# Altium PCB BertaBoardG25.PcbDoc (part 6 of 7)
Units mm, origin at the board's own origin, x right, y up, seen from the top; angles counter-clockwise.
Board outline 160 x 160 mm, 4 copper layers (Top, GND Plane, Power Plane, Bottom), stack 1.344 mm thick; 17 components, 112 nets, 2311 pads, 138 vias.
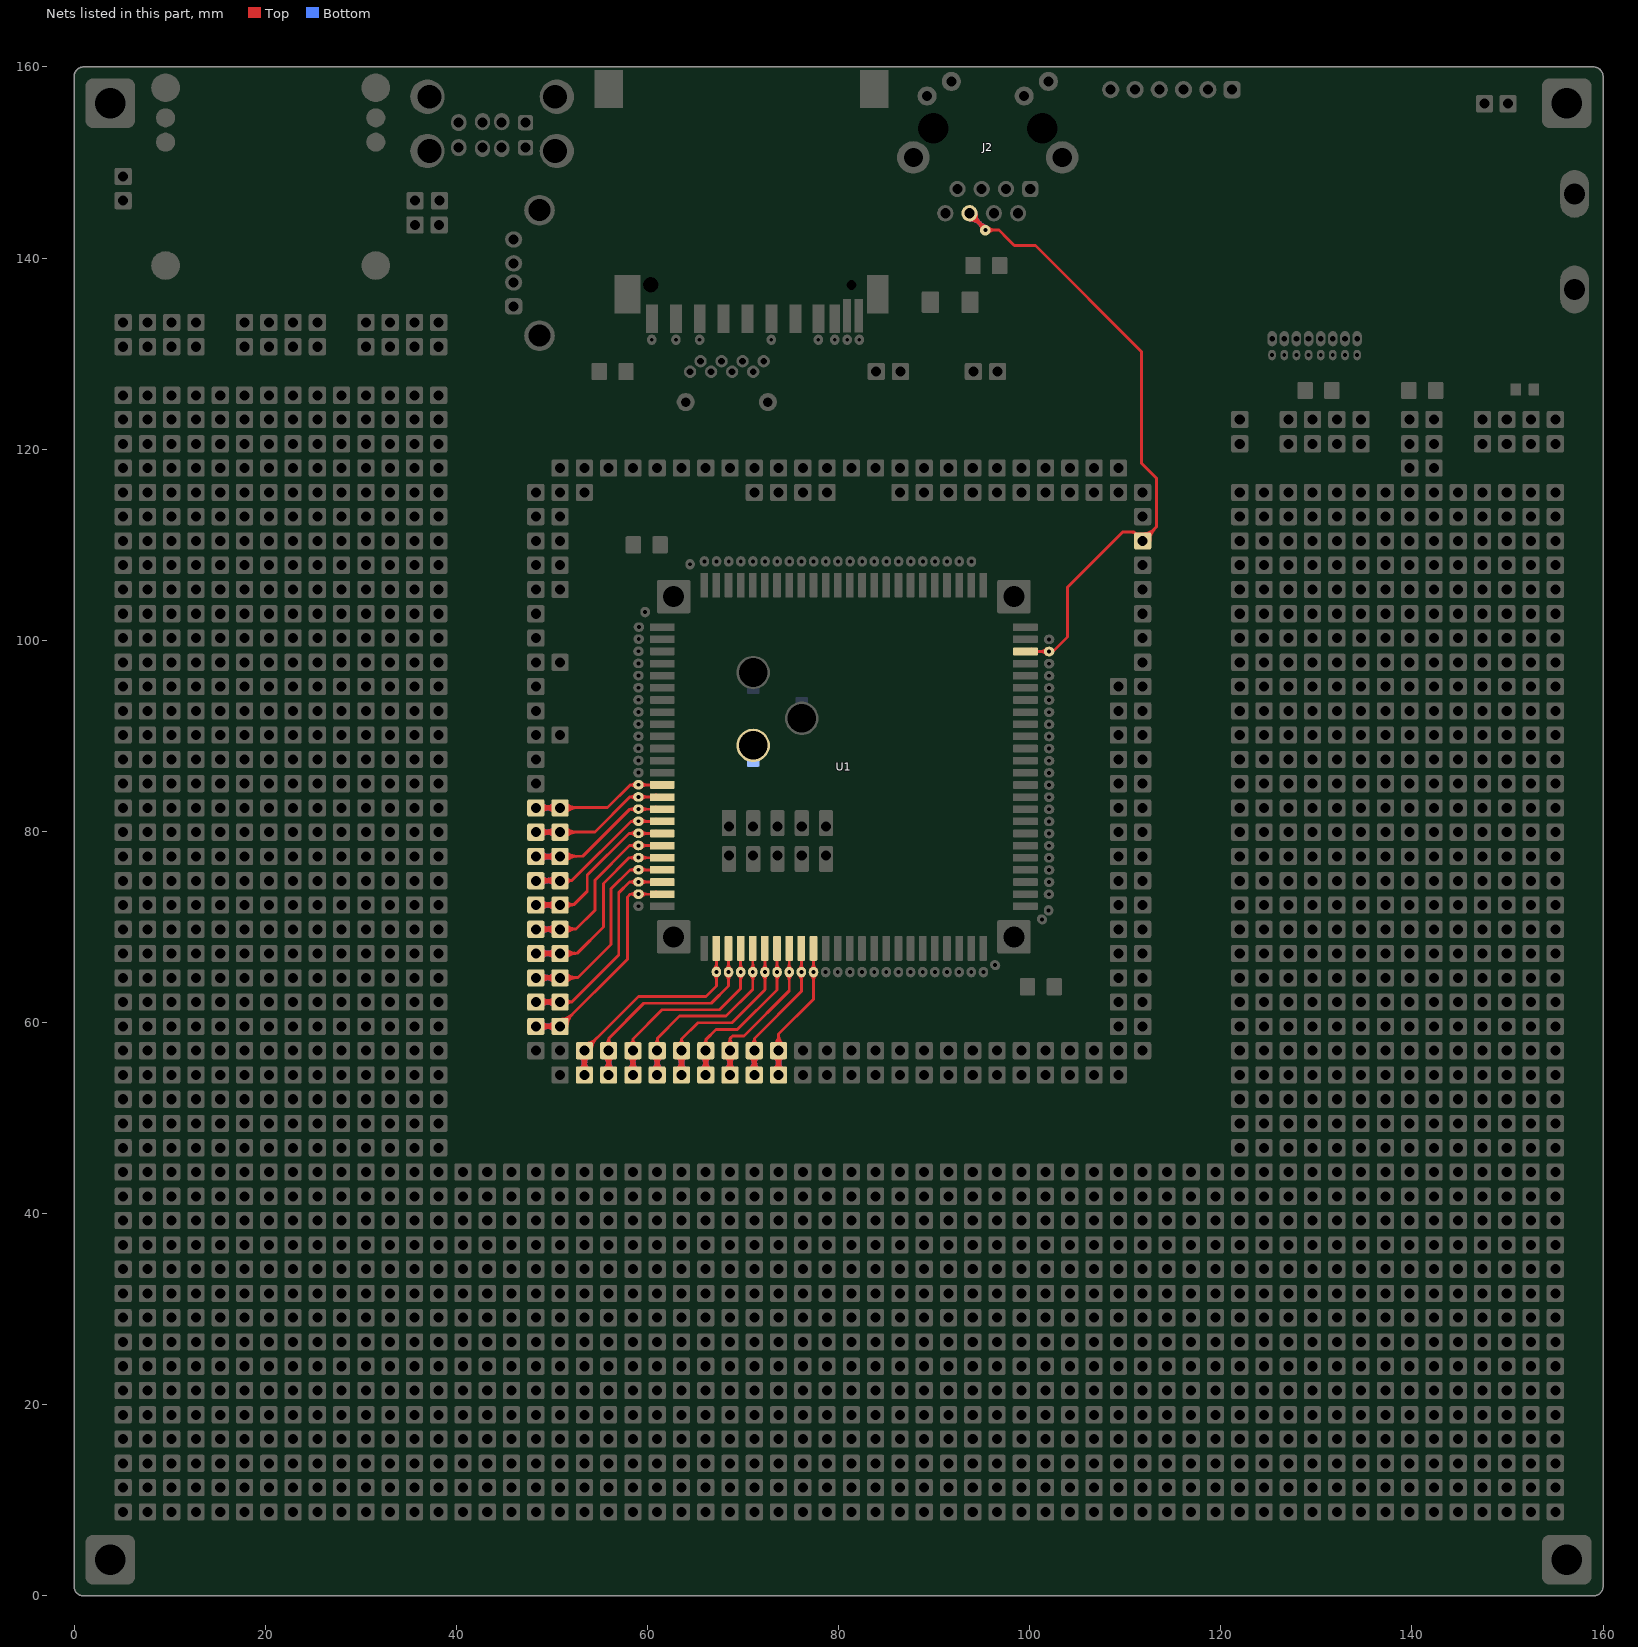
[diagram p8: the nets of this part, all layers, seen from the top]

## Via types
v1: diameter 1.5, hole 0.7, Top to Bottom, tented both sides, 54 vias
v2: diameter 1.1, hole 0.4, Top to Bottom, tented both sides, 49 vias
v3: diameter 1.9, hole 1.05, Top to Bottom, tented both sides, 17 vias
v4: diameter 1.9, hole 1.05, Top to Bottom, 16 vias
v5: diameter 0.9, hole 0.4, Top to Bottom, tented both sides, 2 vias

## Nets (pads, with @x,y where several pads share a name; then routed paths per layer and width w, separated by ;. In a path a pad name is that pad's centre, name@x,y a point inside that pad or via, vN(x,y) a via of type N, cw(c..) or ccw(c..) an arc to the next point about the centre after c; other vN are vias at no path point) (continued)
PC13: pad.0@73.722,54.52 pad.0@73.722,57.06 pad.0@77.379,65.279 U1.N15 | length 52.4
  Top w0.3: pad.0@73.191,55.05 ccw(c71.888,56.353) pad.0@73.731,56.353 ; pad.0@73.191,56.529 cw(c71.888,55.226) pad.0@73.731,55.226 ; pad.0@73.212,57.609 ccw(c72.108,58.8) 73.731,58.8 ; pad.0@73.311,56.432 cw(c72.971,55.913) 73.57,55.753 cw(c74.581,55.482) pad.0@74.081,56.401 ; pad.0@73.359,56.403 cw(c72.829,55.445) 73.886,55.729 cw(c74.524,55.9) pad.0@74.148,56.443 ; pad.0@73.404,54.838 ccw(c72.613,55.629) 73.731,55.629 ; pad.0@73.404,56.741 cw(c72.613,55.95) 73.731,55.95 ; pad.0@73.416,57.39 ccw(c72.745,58.112) 73.731,58.112 ; pad.0@73.475,56.683 cw(c73.21,56.278) 73.678,56.153 ; pad.0@73.731,54.55 73.731,58.8 ; pad.0@73.731,55.272 cw(c75.51,55.272) pad.0@74.252,56.529 ; 73.731,55.583 ccw(c74.785,55.583) pad.0@74.04,54.838 ; 73.731,55.996 cw(c74.785,55.996) pad.0@74.04,56.741 ; pad.0@73.731,56.307 ccw(c75.51,56.307) pad.0@74.252,55.05 ; 73.731,58.095 ccw(c74.718,58.095) pad.0@74.034,57.384 ; 73.776,56.14 cw(c74.267,56.272) pad.0@73.978,56.69 ; pad.0@74.242,57.6 cw(c75.396,58.8) 73.731,58.8 ; pad.0@77.131,64.981 cw(c76.54,64.39) 77.376,64.39 ; pad.0@77.131,65.576 ccw(c76.54,66.167) 77.376,66.167 ; U1.N15@77.199,67.193 cw(c76.773,66.766) 77.376,66.766 cw(c77.98,66.766) U1.N15@77.553,67.193 ; 77.376,64.377 cw(c78.23,64.377) pad.0@77.626,64.981 ; 77.376,66.18 ccw(c78.23,66.18) pad.0@77.626,65.576 ; U1.N15@77.376,67.77 77.376,62.445 73.731,58.8
  Bottom w0.3: pad.0@73.191,55.05 ccw(c71.888,56.353) pad.0@73.731,56.353 ; pad.0@73.191,56.529 cw(c71.888,55.226) pad.0@73.731,55.226 ; pad.0@73.311,56.432 cw(c72.971,55.913) 73.57,55.753 cw(c74.581,55.482) pad.0@74.081,56.401 ; pad.0@73.359,56.403 cw(c72.829,55.445) 73.886,55.729 cw(c74.524,55.9) pad.0@74.148,56.443 ; pad.0@73.404,54.838 ccw(c72.613,55.629) 73.731,55.629 ; pad.0@73.404,56.741 cw(c72.613,55.95) 73.731,55.95 ; pad.0@73.475,56.683 cw(c73.21,56.278) 73.678,56.153 ; pad.0@73.731,54.55 pad.0@73.731,57.09 ; pad.0@73.731,55.272 cw(c75.51,55.272) pad.0@74.252,56.529 ; 73.731,55.583 ccw(c74.785,55.583) pad.0@74.04,54.838 ; 73.731,55.996 cw(c74.785,55.996) pad.0@74.04,56.741 ; pad.0@73.731,56.307 ccw(c75.51,56.307) pad.0@74.252,55.05 ; 73.776,56.14 cw(c74.267,56.272) pad.0@73.978,56.69
PC14: pad.0@71.182,54.52 pad.0@71.182,57.06 pad.0@76.109,65.279 U1.N16 | length 50.2
  Top w0.3: pad.0@70.651,55.05 ccw(c69.348,56.353) pad.0@71.191,56.353 ; pad.0@70.651,56.529 cw(c69.348,55.226) pad.0@71.191,55.226 ; pad.0@70.771,56.432 cw(c70.431,55.913) 71.03,55.753 cw(c72.041,55.482) pad.0@71.541,56.401 ; pad.0@70.819,56.403 cw(c70.289,55.445) 71.346,55.729 cw(c71.984,55.9) pad.0@71.608,56.443 ; pad.0@70.827,57.72 ccw(c70.499,58.33) 71.191,58.33 ; pad.0@70.864,54.838 ccw(c70.073,55.629) 71.191,55.629 ; pad.0@70.864,56.741 cw(c70.073,55.95) 71.191,55.95 ; pad.0@70.935,56.683 cw(c70.67,56.278) 71.138,56.153 ; pad.0@71.191,54.55 71.191,58.33 ; pad.0@71.191,55.272 cw(c72.97,55.272) pad.0@71.712,56.529 ; 71.191,55.583 ccw(c72.245,55.583) pad.0@71.5,54.838 ; 71.191,55.996 cw(c72.245,55.996) pad.0@71.5,56.741 ; pad.0@71.191,56.307 ccw(c72.97,56.307) pad.0@71.712,55.05 ; 71.236,56.14 cw(c71.727,56.272) pad.0@71.438,56.69 ; pad.0@71.551,57.712 cw(c71.901,58.33) 71.191,58.33 ; pad.0@75.861,64.981 cw(c75.27,64.39) 76.106,64.39 ; pad.0@75.861,65.576 ccw(c75.27,66.167) 76.106,66.167 ; U1.N16@75.929,67.193 cw(c75.503,66.766) 76.106,66.766 cw(c76.71,66.766) U1.N16@76.283,67.193 ; 76.106,64.377 cw(c76.96,64.377) pad.0@76.356,64.981 ; 76.106,66.18 ccw(c76.96,66.18) pad.0@76.356,65.576 ; U1.N16@76.106,67.77 76.106,63.245 71.191,58.33
  Bottom w0.3: pad.0@70.651,55.05 ccw(c69.348,56.353) pad.0@71.191,56.353 ; pad.0@70.651,56.529 cw(c69.348,55.226) pad.0@71.191,55.226 ; pad.0@70.771,56.432 cw(c70.431,55.913) 71.03,55.753 cw(c72.041,55.482) pad.0@71.541,56.401 ; pad.0@70.819,56.403 cw(c70.289,55.445) 71.346,55.729 cw(c71.984,55.9) pad.0@71.608,56.443 ; pad.0@70.864,54.838 ccw(c70.073,55.629) 71.191,55.629 ; pad.0@70.864,56.741 cw(c70.073,55.95) 71.191,55.95 ; pad.0@70.935,56.683 cw(c70.67,56.278) 71.138,56.153 ; pad.0@71.191,54.55 pad.0@71.191,57.09 ; pad.0@71.191,55.272 cw(c72.97,55.272) pad.0@71.712,56.529 ; 71.191,55.583 ccw(c72.245,55.583) pad.0@71.5,54.838 ; 71.191,55.996 cw(c72.245,55.996) pad.0@71.5,56.741 ; pad.0@71.191,56.307 ccw(c72.97,56.307) pad.0@71.712,55.05 ; 71.236,56.14 cw(c71.727,56.272) pad.0@71.438,56.69
PC15: pad.0@68.642,54.52 pad.0@68.642,57.06 pad.0@74.839,65.279 U1.N17 | length 51.5
  Top w0.3: pad.0@68.111,55.05 ccw(c66.808,56.353) pad.0@68.651,56.353 ; pad.0@68.111,56.529 cw(c66.808,55.226) pad.0@68.651,55.226 ; pad.0@68.231,56.432 cw(c67.891,55.913) 68.49,55.753 cw(c69.501,55.482) pad.0@69.001,56.401 ; pad.0@68.277,57.715 ccw(c67.924,58.35) 68.651,58.35 ; pad.0@68.279,56.403 cw(c67.749,55.445) 68.806,55.729 cw(c69.444,55.9) pad.0@69.068,56.443 ; pad.0@68.324,54.838 ccw(c67.533,55.629) 68.651,55.629 ; pad.0@68.324,56.741 cw(c67.533,55.95) 68.651,55.95 ; pad.0@68.395,56.683 cw(c68.13,56.278) 68.598,56.153 ; pad.0@68.651,54.55 68.651,58.35 ; pad.0@68.651,55.272 cw(c70.43,55.272) pad.0@69.172,56.529 ; 68.651,55.583 ccw(c69.705,55.583) pad.0@68.96,54.838 ; 68.651,55.996 cw(c69.705,55.996) pad.0@68.96,56.741 ; pad.0@68.651,56.307 ccw(c70.43,56.307) pad.0@69.172,55.05 ; 68.696,56.14 cw(c69.187,56.272) pad.0@68.898,56.69 ; pad.0@69.02,57.707 cw(c69.396,58.35) 68.651,58.35 ; pad.0@74.591,64.981 cw(c74,64.39) 74.836,64.39 ; pad.0@74.591,65.576 ccw(c74,66.167) 74.836,66.167 ; U1.N17@74.659,67.193 cw(c74.233,66.766) 74.836,66.766 cw(c75.44,66.766) U1.N17@75.013,67.193 ; 74.836,64.377 cw(c75.69,64.377) pad.0@75.086,64.981 ; 74.836,66.18 ccw(c75.69,66.18) pad.0@75.086,65.576 ; U1.N17@74.836,67.77 74.836,63.335 70.101,58.6 68.916,58.6 68.726,58.41 68.711,58.41 68.651,58.35
  Bottom w0.3: pad.0@68.111,55.05 ccw(c66.808,56.353) pad.0@68.651,56.353 ; pad.0@68.111,56.529 cw(c66.808,55.226) pad.0@68.651,55.226 ; pad.0@68.231,56.432 cw(c67.891,55.913) 68.49,55.753 cw(c69.501,55.482) pad.0@69.001,56.401 ; pad.0@68.279,56.403 cw(c67.749,55.445) 68.806,55.729 cw(c69.444,55.9) pad.0@69.068,56.443 ; pad.0@68.324,54.838 ccw(c67.533,55.629) 68.651,55.629 ; pad.0@68.324,56.741 cw(c67.533,55.95) 68.651,55.95 ; pad.0@68.395,56.683 cw(c68.13,56.278) 68.598,56.153 ; pad.0@68.651,54.55 pad.0@68.651,57.09 ; pad.0@68.651,55.272 cw(c70.43,55.272) pad.0@69.172,56.529 ; 68.651,55.583 ccw(c69.705,55.583) pad.0@68.96,54.838 ; 68.651,55.996 cw(c69.705,55.996) pad.0@68.96,56.741 ; pad.0@68.651,56.307 ccw(c70.43,56.307) pad.0@69.172,55.05 ; 68.696,56.14 cw(c69.187,56.272) pad.0@68.898,56.69
PC16: pad.0@66.102,54.52 pad.0@66.102,57.06 pad.0@73.569,65.279 U1.N18 | length 52.2
  Top w0.3: pad.0@65.571,55.05 ccw(c64.268,56.353) pad.0@66.111,56.353 ; pad.0@65.571,56.529 cw(c64.268,55.226) pad.0@66.111,55.226 ; pad.0@65.691,56.432 cw(c65.351,55.913) 65.95,55.753 cw(c66.961,55.482) pad.0@66.461,56.401 ; pad.0@65.739,56.403 cw(c65.209,55.445) 66.266,55.729 cw(c66.904,55.9) pad.0@66.528,56.443 ; pad.0@65.784,54.838 ccw(c64.993,55.629) 66.111,55.629 ; pad.0@65.784,56.741 cw(c64.993,55.95) 66.111,55.95 ; pad.0@65.807,57.749 ccw(c65.609,58.21) 66.111,58.21 ; pad.0@65.855,56.683 cw(c65.59,56.278) 66.058,56.153 ; pad.0@66.111,54.55 66.111,58.21 ; pad.0@66.111,55.272 cw(c67.89,55.272) pad.0@66.632,56.529 ; 66.111,55.583 ccw(c67.165,55.583) pad.0@66.42,54.838 ; 66.111,55.996 cw(c67.165,55.996) pad.0@66.42,56.741 ; pad.0@66.111,56.307 ccw(c67.89,56.307) pad.0@66.632,55.05 ; 66.156,56.14 cw(c66.647,56.272) pad.0@66.358,56.69 ; pad.0@66.412,57.742 cw(c66.626,58.21) 66.111,58.21 ; pad.0@73.321,64.981 cw(c72.73,64.39) 73.566,64.39 ; pad.0@73.321,65.576 ccw(c72.73,66.167) 73.566,66.167 ; U1.N18@73.389,67.193 cw(c72.963,66.766) 73.566,66.766 cw(c74.17,66.766) U1.N18@73.743,67.193 ; 73.566,64.377 cw(c74.42,64.377) pad.0@73.816,64.981 ; 73.566,66.18 ccw(c74.42,66.18) pad.0@73.816,65.576 ; U1.N18@73.566,67.77 73.566,63.425 69.408,59.267 67.168,59.267 66.111,58.21
  Bottom w0.3: pad.0@65.571,55.05 ccw(c64.268,56.353) pad.0@66.111,56.353 ; pad.0@65.571,56.529 cw(c64.268,55.226) pad.0@66.111,55.226 ; pad.0@65.691,56.432 cw(c65.351,55.913) 65.95,55.753 cw(c66.961,55.482) pad.0@66.461,56.401 ; pad.0@65.739,56.403 cw(c65.209,55.445) 66.266,55.729 cw(c66.904,55.9) pad.0@66.528,56.443 ; pad.0@65.784,54.838 ccw(c64.993,55.629) 66.111,55.629 ; pad.0@65.784,56.741 cw(c64.993,55.95) 66.111,55.95 ; pad.0@65.855,56.683 cw(c65.59,56.278) 66.058,56.153 ; pad.0@66.111,54.55 pad.0@66.111,57.09 ; pad.0@66.111,55.272 cw(c67.89,55.272) pad.0@66.632,56.529 ; 66.111,55.583 ccw(c67.165,55.583) pad.0@66.42,54.838 ; 66.111,55.996 cw(c67.165,55.996) pad.0@66.42,56.741 ; pad.0@66.111,56.307 ccw(c67.89,56.307) pad.0@66.632,55.05 ; 66.156,56.14 cw(c66.647,56.272) pad.0@66.358,56.69
PC17: pad.0@63.562,54.52 pad.0@63.562,57.06 pad.0@72.299,65.279 U1.N19 | length 53.7
  Top w0.3: pad.0@63.031,55.05 ccw(c61.728,56.353) pad.0@63.571,56.353 ; pad.0@63.031,56.529 cw(c61.728,55.226) pad.0@63.571,55.226 ; pad.0@63.151,56.432 cw(c62.811,55.913) 63.41,55.753 cw(c64.421,55.482) pad.0@63.921,56.401 ; pad.0@63.199,56.403 cw(c62.669,55.445) 63.726,55.729 cw(c64.364,55.9) pad.0@63.988,56.443 ; pad.0@63.235,57.735 ccw(c62.976,58.27) 63.571,58.27 ; pad.0@63.244,54.838 ccw(c62.453,55.629) 63.571,55.629 ; pad.0@63.244,56.741 cw(c62.453,55.95) 63.571,55.95 ; pad.0@63.315,56.683 cw(c63.05,56.278) 63.518,56.153 ; pad.0@63.571,54.55 63.571,58.27 ; pad.0@63.571,55.272 cw(c65.35,55.272) pad.0@64.092,56.529 ; 63.571,55.583 ccw(c64.625,55.583) pad.0@63.88,54.838 ; 63.571,55.996 cw(c64.625,55.996) pad.0@63.88,56.741 ; pad.0@63.571,56.307 ccw(c65.35,56.307) pad.0@64.092,55.05 ; 63.616,56.14 cw(c64.107,56.272) pad.0@63.818,56.69 ; pad.0@63.903,57.727 cw(c64.181,58.27) 63.571,58.27 ; pad.0@72.051,64.981 cw(c71.46,64.39) 72.296,64.39 ; pad.0@72.051,65.576 ccw(c71.46,66.167) 72.296,66.167 ; U1.N19@72.119,67.193 cw(c71.693,66.766) 72.296,66.766 cw(c72.9,66.766) U1.N19@72.473,67.193 ; 72.296,64.377 cw(c73.15,64.377) pad.0@72.546,64.981 ; 72.296,66.18 ccw(c73.15,66.18) pad.0@72.546,65.576 ; U1.N19@72.296,67.77 72.296,63.445 68.839,59.988 65.289,59.988 63.571,58.27
  Bottom w0.3: pad.0@63.031,55.05 ccw(c61.728,56.353) pad.0@63.571,56.353 ; pad.0@63.031,56.529 cw(c61.728,55.226) pad.0@63.571,55.226 ; pad.0@63.151,56.432 cw(c62.811,55.913) 63.41,55.753 cw(c64.421,55.482) pad.0@63.921,56.401 ; pad.0@63.199,56.403 cw(c62.669,55.445) 63.726,55.729 cw(c64.364,55.9) pad.0@63.988,56.443 ; pad.0@63.244,54.838 ccw(c62.453,55.629) 63.571,55.629 ; pad.0@63.244,56.741 cw(c62.453,55.95) 63.571,55.95 ; pad.0@63.315,56.683 cw(c63.05,56.278) 63.518,56.153 ; pad.0@63.571,54.55 pad.0@63.571,57.09 ; pad.0@63.571,55.272 cw(c65.35,55.272) pad.0@64.092,56.529 ; 63.571,55.583 ccw(c64.625,55.583) pad.0@63.88,54.838 ; 63.571,55.996 cw(c64.625,55.996) pad.0@63.88,56.741 ; pad.0@63.571,56.307 ccw(c65.35,56.307) pad.0@64.092,55.05 ; 63.616,56.14 cw(c64.107,56.272) pad.0@63.818,56.69
PC18: pad.0@61.022,54.52 pad.0@61.022,57.06 pad.0@71.029,65.279 U1.N20 | length 55.1
  Top w0.3: pad.0@60.491,55.05 ccw(c59.188,56.353) pad.0@61.031,56.353 ; pad.0@60.491,56.529 cw(c59.188,55.226) pad.0@61.031,55.226 ; pad.0@60.611,56.432 cw(c60.271,55.913) 60.87,55.753 cw(c61.881,55.482) pad.0@61.381,56.401 ; pad.0@60.659,56.403 cw(c60.129,55.445) 61.186,55.729 cw(c61.824,55.9) pad.0@61.448,56.443 ; pad.0@60.666,57.72 ccw(c60.338,58.33) 61.031,58.33 ; pad.0@60.704,54.838 ccw(c59.913,55.629) 61.031,55.629 ; pad.0@60.704,56.741 cw(c59.913,55.95) 61.031,55.95 ; pad.0@60.775,56.683 cw(c60.51,56.278) 60.978,56.153 ; pad.0@61.031,54.55 61.031,58.33 ; pad.0@61.031,55.272 cw(c62.81,55.272) pad.0@61.552,56.529 ; 61.031,55.583 ccw(c62.085,55.583) pad.0@61.34,54.838 ; 61.031,55.996 cw(c62.085,55.996) pad.0@61.34,56.741 ; pad.0@61.031,56.307 ccw(c62.81,56.307) pad.0@61.552,55.05 ; 61.076,56.14 cw(c61.567,56.272) pad.0@61.278,56.69 ; pad.0@61.391,57.712 cw(c61.742,58.33) 61.031,58.33 ; pad.0@70.781,64.981 cw(c70.19,64.39) 71.026,64.39 ; pad.0@70.781,65.576 ccw(c70.19,66.167) 71.026,66.167 ; U1.N20@70.849,67.193 cw(c70.423,66.766) 71.026,66.766 cw(c71.63,66.766) U1.N20@71.203,67.193 ; 71.026,64.377 cw(c71.88,64.377) pad.0@71.276,64.981 ; 71.026,66.18 ccw(c71.88,66.18) pad.0@71.276,65.576 ; U1.N20@71.026,67.77 71.026,63.465 68.234,60.673 63.374,60.673 61.031,58.33
  Bottom w0.3: pad.0@60.491,55.05 ccw(c59.188,56.353) pad.0@61.031,56.353 ; pad.0@60.491,56.529 cw(c59.188,55.226) pad.0@61.031,55.226 ; pad.0@60.611,56.432 cw(c60.271,55.913) 60.87,55.753 cw(c61.881,55.482) pad.0@61.381,56.401 ; pad.0@60.659,56.403 cw(c60.129,55.445) 61.186,55.729 cw(c61.824,55.9) pad.0@61.448,56.443 ; pad.0@60.704,54.838 ccw(c59.913,55.629) 61.031,55.629 ; pad.0@60.704,56.741 cw(c59.913,55.95) 61.031,55.95 ; pad.0@60.775,56.683 cw(c60.51,56.278) 60.978,56.153 ; pad.0@61.031,54.55 pad.0@61.031,57.09 ; pad.0@61.031,55.272 cw(c62.81,55.272) pad.0@61.552,56.529 ; 61.031,55.583 ccw(c62.085,55.583) pad.0@61.34,54.838 ; 61.031,55.996 cw(c62.085,55.996) pad.0@61.34,56.741 ; pad.0@61.031,56.307 ccw(c62.81,56.307) pad.0@61.552,55.05 ; 61.076,56.14 cw(c61.567,56.272) pad.0@61.278,56.69
PC19: pad.0@58.482,54.52 pad.0@58.482,57.06 pad.0@69.759,65.279 U1.N21 | length 56.2
  Top w0.3: pad.0@57.951,55.05 ccw(c56.648,56.353) pad.0@58.491,56.353 ; pad.0@57.951,56.529 cw(c56.648,55.226) pad.0@58.491,55.226 ; pad.0@58.071,56.432 cw(c57.731,55.913) 58.33,55.753 cw(c59.341,55.482) pad.0@58.841,56.401 ; pad.0@58.119,56.403 cw(c57.589,55.445) 58.646,55.729 cw(c59.284,55.9) pad.0@58.908,56.443 ; pad.0@58.145,57.73 ccw(c57.864,58.29) 58.491,58.29 ; pad.0@58.164,54.838 ccw(c57.373,55.629) 58.491,55.629 ; pad.0@58.164,56.741 cw(c57.373,55.95) 58.491,55.95 ; pad.0@58.235,56.683 cw(c57.97,56.278) 58.438,56.153 ; pad.0@58.491,54.55 58.491,58.29 ; pad.0@58.491,55.272 cw(c60.27,55.272) pad.0@59.012,56.529 ; 58.491,55.583 ccw(c59.545,55.583) pad.0@58.8,54.838 ; 58.491,55.996 cw(c59.545,55.996) pad.0@58.8,56.741 ; pad.0@58.491,56.307 ccw(c60.27,56.307) pad.0@59.012,55.05 ; 58.536,56.14 cw(c59.027,56.272) pad.0@58.738,56.69 ; pad.0@58.833,57.722 cw(c59.134,58.29) 58.491,58.29 ; pad.0@69.511,64.981 cw(c68.92,64.39) 69.756,64.39 ; pad.0@69.511,65.576 ccw(c68.92,66.167) 69.756,66.167 ; U1.N21@69.579,67.193 cw(c69.153,66.766) 69.756,66.766 cw(c70.36,66.766) U1.N21@69.933,67.193 ; 69.756,64.377 cw(c70.61,64.377) pad.0@70.006,64.981 ; 69.756,66.18 ccw(c70.61,66.18) pad.0@70.006,65.576 ; U1.N21@69.756,67.77 69.756,63.535 67.558,61.337 61.538,61.337 58.491,58.29
  Bottom w0.3: pad.0@57.951,55.05 ccw(c56.648,56.353) pad.0@58.491,56.353 ; pad.0@57.951,56.529 cw(c56.648,55.226) pad.0@58.491,55.226 ; pad.0@58.071,56.432 cw(c57.731,55.913) 58.33,55.753 cw(c59.341,55.482) pad.0@58.841,56.401 ; pad.0@58.119,56.403 cw(c57.589,55.445) 58.646,55.729 cw(c59.284,55.9) pad.0@58.908,56.443 ; pad.0@58.164,54.838 ccw(c57.373,55.629) 58.491,55.629 ; pad.0@58.164,56.741 cw(c57.373,55.95) 58.491,55.95 ; pad.0@58.235,56.683 cw(c57.97,56.278) 58.438,56.153 ; pad.0@58.491,54.55 pad.0@58.491,57.09 ; pad.0@58.491,55.272 cw(c60.27,55.272) pad.0@59.012,56.529 ; 58.491,55.583 ccw(c59.545,55.583) pad.0@58.8,54.838 ; 58.491,55.996 cw(c59.545,55.996) pad.0@58.8,56.741 ; pad.0@58.491,56.307 ccw(c60.27,56.307) pad.0@59.012,55.05 ; 58.536,56.14 cw(c59.027,56.272) pad.0@58.738,56.69
PC20: pad.0@55.942,54.52 pad.0@55.942,57.06 pad.0@68.489,65.279 U1.N22 | length 57.5
  Top w0.3: pad.0@55.411,55.05 ccw(c54.108,56.353) pad.0@55.951,56.353 ; pad.0@55.411,56.529 cw(c54.108,55.226) pad.0@55.951,55.226 ; pad.0@55.531,56.432 cw(c55.191,55.913) 55.79,55.753 cw(c56.801,55.482) pad.0@56.301,56.401 ; pad.0@55.577,57.715 ccw(c55.224,58.35) 55.951,58.35 ; pad.0@55.579,56.403 cw(c55.049,55.445) 56.106,55.729 cw(c56.744,55.9) pad.0@56.368,56.443 ; pad.0@55.624,54.838 ccw(c54.833,55.629) 55.951,55.629 ; pad.0@55.624,56.741 cw(c54.833,55.95) 55.951,55.95 ; pad.0@55.695,56.683 cw(c55.43,56.278) 55.898,56.153 ; pad.0@55.951,54.55 55.951,58.35 ; pad.0@55.951,55.272 cw(c57.73,55.272) pad.0@56.472,56.529 ; 55.951,55.583 ccw(c57.005,55.583) pad.0@56.26,54.838 ; 55.951,55.996 cw(c57.005,55.996) pad.0@56.26,56.741 ; pad.0@55.951,56.307 ccw(c57.73,56.307) pad.0@56.472,55.05 ; 55.996,56.14 cw(c56.487,56.272) pad.0@56.198,56.69 ; pad.0@56.32,57.707 cw(c56.696,58.35) 55.951,58.35 ; pad.0@68.241,64.981 cw(c67.65,64.39) 68.486,64.39 ; pad.0@68.241,65.576 ccw(c67.65,66.167) 68.486,66.167 ; U1.N22@68.309,67.193 cw(c67.883,66.766) 68.486,66.766 cw(c69.09,66.766) U1.N22@68.663,67.193 ; 68.486,64.377 cw(c69.34,64.377) pad.0@68.736,64.981 ; 68.486,66.18 ccw(c69.34,66.18) pad.0@68.736,65.576 ; U1.N22@68.486,67.77 68.486,63.835 66.673,62.022 59.623,62.022 55.951,58.35
  Bottom w0.3: pad.0@55.411,55.05 ccw(c54.108,56.353) pad.0@55.951,56.353 ; pad.0@55.411,56.529 cw(c54.108,55.226) pad.0@55.951,55.226 ; pad.0@55.531,56.432 cw(c55.191,55.913) 55.79,55.753 cw(c56.801,55.482) pad.0@56.301,56.401 ; pad.0@55.579,56.403 cw(c55.049,55.445) 56.106,55.729 cw(c56.744,55.9) pad.0@56.368,56.443 ; pad.0@55.624,54.838 ccw(c54.833,55.629) 55.951,55.629 ; pad.0@55.624,56.741 cw(c54.833,55.95) 55.951,55.95 ; pad.0@55.695,56.683 cw(c55.43,56.278) 55.898,56.153 ; pad.0@55.951,54.55 pad.0@55.951,57.09 ; pad.0@55.951,55.272 cw(c57.73,55.272) pad.0@56.472,56.529 ; 55.951,55.583 ccw(c57.005,55.583) pad.0@56.26,54.838 ; 55.951,55.996 cw(c57.005,55.996) pad.0@56.26,56.741 ; pad.0@55.951,56.307 ccw(c57.73,56.307) pad.0@56.472,55.05 ; 55.996,56.14 cw(c56.487,56.272) pad.0@56.198,56.69
PC21: pad.0@53.402,54.52 pad.0@53.402,57.06 pad.0@67.219,65.304 U1.N23 | length 61.1
  Top w0.3: pad.0@52.871,55.05 ccw(c51.568,56.353) pad.0@53.411,56.353 ; pad.0@52.871,56.529 cw(c51.568,55.226) pad.0@53.411,55.226 ; pad.0@52.991,55.147 ccw(c52.651,55.666) 53.25,55.826 ccw(c54.261,56.097) pad.0@53.761,55.178 ; pad.0@53.039,55.176 ccw(c52.509,56.134) 53.566,55.85 ccw(c54.204,55.68) pad.0@53.828,55.136 ; pad.0@53.084,54.838 ccw(c52.293,55.629) 53.411,55.629 ; pad.0@53.084,56.741 cw(c52.293,55.95) 53.411,55.95 ; pad.0@53.155,54.896 ccw(c52.89,55.301) 53.358,55.426 ; pad.0@53.402,57.51 ccw(c53.402,58.546) pad.0@54.135,57.813 ; pad.0@53.402,57.81 ccw(c53.402,59.57) 54.647,58.325 ; pad.0@53.411,54.55 53.411,57.09 59.063,62.742 66.143,62.742 67.216,63.815 U1.N23@67.216,67.77 ; pad.0@53.411,55.272 cw(c55.19,55.272) pad.0@53.932,56.529 ; 53.411,55.583 ccw(c54.465,55.583) pad.0@53.72,54.838 ; 53.411,55.996 cw(c54.465,55.996) pad.0@53.72,56.741 ; pad.0@53.411,56.307 ccw(c55.19,56.307) pad.0@53.932,55.05 ; 53.456,55.439 ccw(c53.947,55.308) pad.0@53.658,54.89 ; pad.0@53.852,57.06 cw(c54.988,57.06) pad.0@54.185,57.863 ; pad.0@54.152,57.06 cw(c56.012,57.06) 54.697,58.375 ; pad.0@66.971,65.006 cw(c66.38,64.415) 67.216,64.415 ; pad.0@66.971,65.601 ccw(c66.38,66.193) 67.216,66.193 ; U1.N23@67.039,67.193 cw(c66.613,66.766) 67.216,66.766 cw(c67.82,66.766) U1.N23@67.393,67.193 ; 67.216,64.403 cw(c68.07,64.403) pad.0@67.466,65.006 ; 67.216,66.205 ccw(c68.07,66.205) pad.0@67.466,65.601
  Bottom w0.3: pad.0@52.871,55.05 ccw(c51.568,56.353) pad.0@53.411,56.353 ; pad.0@52.871,56.529 cw(c51.568,55.226) pad.0@53.411,55.226 ; pad.0@52.991,55.147 ccw(c52.651,55.666) 53.25,55.826 ccw(c54.261,56.097) pad.0@53.761,55.178 ; pad.0@53.039,55.176 ccw(c52.509,56.134) 53.566,55.85 ccw(c54.204,55.68) pad.0@53.828,55.136 ; pad.0@53.084,54.838 ccw(c52.293,55.629) 53.411,55.629 ; pad.0@53.084,56.741 cw(c52.293,55.95) 53.411,55.95 ; pad.0@53.155,54.896 ccw(c52.89,55.301) 53.358,55.426 ; pad.0@53.411,54.55 pad.0@53.411,57.09 ; pad.0@53.411,55.272 cw(c55.19,55.272) pad.0@53.932,56.529 ; 53.411,55.583 ccw(c54.465,55.583) pad.0@53.72,54.838 ; 53.411,55.996 cw(c54.465,55.996) pad.0@53.72,56.741 ; pad.0@53.411,56.307 ccw(c55.19,56.307) pad.0@53.932,55.05 ; 53.456,55.439 ccw(c53.947,55.308) pad.0@53.658,54.89
PC22: pad.0@48.322,59.6 pad.0@50.862,59.6 pad.0@59.073,73.44 U1.E2 | length 59.4
  Top w0.3: pad.0@48.331,59.63 50.911,59.63 57.901,66.619 57.901,73.149 58.186,73.435 ; pad.0@48.64,59.281 cw(c49.481,58.44) 49.481,59.63 ; pad.0@48.64,59.918 ccw(c49.335,60.613) 49.335,59.63 ; pad.0@48.852,59.069 cw(c50.205,57.716) pad.0@50.205,59.63 ; pad.0@48.852,60.13 ccw(c50.06,61.337) pad.0@50.06,59.63 ; pad.0@48.978,59.63 cw(c48.978,57.716) pad.0@50.331,59.069 ; pad.0@49.124,59.63 ccw(c49.124,61.337) pad.0@50.331,60.13 ; 49.703,59.63 cw(c49.703,58.44) pad.0@50.544,59.281 ; 49.848,59.63 ccw(c49.848,60.613) pad.0@50.544,59.918 ; 49.928,59.665 ccw(c50.067,60.183) pad.0@50.499,59.866 ; pad.0@50.201,59.954 cw(c49.324,60.423) 49.581,59.463 cw(c49.731,58.905) pad.0@50.223,59.207 ; pad.0@50.208,59.232 ccw(c49.207,58.67) 49.504,59.778 ccw(c49.687,60.461) pad.0@50.257,60.043 ; pad.0@50.862,60.05 ccw(c50.862,61.183) pad.0@51.663,60.381 ; pad.0@50.862,60.35 ccw(c50.862,62.207) 52.175,60.894 ; pad.0@51.312,59.6 cw(c52.352,59.6) pad.0@51.616,60.335 ; pad.0@51.612,59.6 cw(c53.376,59.6) 52.128,60.847 ; 58.192,73.435 cw(c58.192,72.608) pad.0@58.776,73.193 ; pad.0@58.772,73.683 cw(c58.186,74.248) 58.186,73.435 ; pad.0@59.371,73.193 cw(c59.955,72.608) 59.955,73.435 ; pad.0@59.371,73.688 ccw(c59.982,74.298) 59.982,73.435 ; U1.E2@60.289,73.435 ccw(c60.289,74.297) U1.E2@60.899,73.687 ; U1.E2@61.013,73.435 ccw(c61.013,73.573) U1.E2@61.111,73.475 ; U1.E2@61.551,73.435 58.186,73.435
  Bottom w0.3: pad.0@48.331,59.63 pad.0@50.871,59.63 ; pad.0@48.64,59.281 cw(c49.481,58.44) 49.481,59.63 ; pad.0@48.64,59.918 ccw(c49.335,60.613) 49.335,59.63 ; pad.0@48.852,59.069 cw(c50.205,57.716) pad.0@50.205,59.63 ; pad.0@48.852,60.13 ccw(c50.06,61.337) pad.0@50.06,59.63 ; pad.0@48.978,59.63 cw(c48.978,57.716) pad.0@50.331,59.069 ; pad.0@49.124,59.63 ccw(c49.124,61.337) pad.0@50.331,60.13 ; 49.703,59.63 cw(c49.703,58.44) pad.0@50.544,59.281 ; 49.848,59.63 ccw(c49.848,60.613) pad.0@50.544,59.918 ; 49.928,59.665 ccw(c50.067,60.183) pad.0@50.499,59.866 ; pad.0@50.201,59.954 cw(c49.324,60.423) 49.581,59.463 cw(c49.731,58.905) pad.0@50.223,59.207 ; pad.0@50.208,59.232 ccw(c49.207,58.67) 49.504,59.778 ccw(c49.687,60.461) pad.0@50.257,60.043
PC23: pad.0@48.322,62.14 pad.0@50.862,62.14 pad.0@59.06,74.722 U1.E3 | length 55.7
  Top w0.3: pad.0@48.331,62.17 52.081,62.17 ; pad.0@48.64,61.821 cw(c49.481,60.98) 49.481,62.17 ; pad.0@48.64,62.458 ccw(c49.335,63.153) 49.335,62.17 ; pad.0@48.852,61.609 cw(c50.205,60.256) pad.0@50.205,62.17 ; pad.0@48.852,62.67 ccw(c50.06,63.877) pad.0@50.06,62.17 ; pad.0@48.978,62.17 cw(c48.978,60.256) pad.0@50.331,61.609 ; pad.0@49.124,62.17 ccw(c49.124,63.877) pad.0@50.331,62.67 ; 49.703,62.17 cw(c49.703,60.98) pad.0@50.544,61.821 ; 49.848,62.17 ccw(c49.848,63.153) pad.0@50.544,62.458 ; 49.928,62.205 ccw(c50.067,62.723) pad.0@50.499,62.406 ; pad.0@50.201,62.494 cw(c49.324,62.963) 49.581,62.003 cw(c49.731,61.445) pad.0@50.223,61.747 ; pad.0@50.208,61.772 ccw(c49.207,61.21) 49.504,62.318 ccw(c49.687,63.001) pad.0@50.257,62.583 ; pad.0@51.518,62.502 ccw(c52.081,62.812) 52.081,62.17 ; pad.0@51.543,61.825 cw(c52.081,61.577) 52.081,62.17 ; 58.207,74.705 cw(c58.207,73.919) pad.0@58.762,74.475 ; pad.0@58.762,74.969 cw(c58.126,75.601) 58.126,74.705 ; pad.0@59.357,74.475 cw(c59.913,73.919) 59.913,74.705 ; pad.0@59.357,74.97 ccw(c59.997,75.609) 59.997,74.705 ; U1.E3@60.289,74.705 ccw(c60.289,75.567) U1.E3@60.899,74.957 ; U1.E3@61.013,74.705 ccw(c61.013,74.843) U1.E3@61.111,74.745 ; U1.E3@61.551,74.705 58.126,74.705 ; 52.081,62.17 57.001,67.089 57.001,73.579 58.126,74.705
  Bottom w0.3: pad.0@48.331,62.17 pad.0@50.871,62.17 ; pad.0@48.64,61.821 cw(c49.481,60.98) 49.481,62.17 ; pad.0@48.64,62.458 ccw(c49.335,63.153) 49.335,62.17 ; pad.0@48.852,61.609 cw(c50.205,60.256) pad.0@50.205,62.17 ; pad.0@48.852,62.67 ccw(c50.06,63.877) pad.0@50.06,62.17 ; pad.0@48.978,62.17 cw(c48.978,60.256) pad.0@50.331,61.609 ; pad.0@49.124,62.17 ccw(c49.124,63.877) pad.0@50.331,62.67 ; 49.703,62.17 cw(c49.703,60.98) pad.0@50.544,61.821 ; 49.848,62.17 ccw(c49.848,63.153) pad.0@50.544,62.458 ; 49.928,62.205 ccw(c50.067,62.723) pad.0@50.499,62.406 ; pad.0@50.201,62.494 cw(c49.324,62.963) 49.581,62.003 cw(c49.731,61.445) pad.0@50.223,61.747 ; pad.0@50.208,61.772 ccw(c49.207,61.21) 49.504,62.318 ccw(c49.687,63.001) pad.0@50.257,62.583
PC24: pad.0@48.322,64.68 pad.0@50.862,64.68 pad.0@59.06,75.992 U1.E4 | length 57.9
  Top w0.3: pad.0@48.331,64.71 52.751,64.71 56.201,68.159 56.201,73.999 58.176,75.975 ; pad.0@48.64,64.361 cw(c49.481,63.52) 49.481,64.71 ; pad.0@48.64,64.998 ccw(c49.335,65.693) 49.335,64.71 ; pad.0@48.852,64.149 cw(c50.205,62.796) pad.0@50.205,64.71 ; pad.0@48.852,65.21 ccw(c50.06,66.417) pad.0@50.06,64.71 ; pad.0@48.978,64.71 cw(c48.978,62.796) pad.0@50.331,64.149 ; pad.0@49.124,64.71 ccw(c49.124,66.417) pad.0@50.331,65.21 ; 49.703,64.71 cw(c49.703,63.52) pad.0@50.544,64.361 ; 49.848,64.71 ccw(c49.848,65.693) pad.0@50.544,64.998 ; 49.928,64.745 ccw(c50.067,65.263) pad.0@50.499,64.946 ; pad.0@50.201,65.034 cw(c49.324,65.503) 49.581,64.543 cw(c49.731,63.985) pad.0@50.223,64.287 ; pad.0@50.208,64.312 ccw(c49.207,63.75) 49.504,64.858 ccw(c49.687,65.541) pad.0@50.257,65.123 ; pad.0@51.18,64.361 cw(c52.021,63.52) 52.021,64.71 ; pad.0@51.18,64.998 ccw(c51.875,65.693) 51.875,64.71 ; pad.0@51.392,64.149 cw(c52.745,62.796) 52.745,64.71 ; pad.0@51.392,65.21 ccw(c52.6,66.417) 52.6,64.71 ; 58.207,75.975 cw(c58.207,75.189) pad.0@58.762,75.745 ; pad.0@58.752,76.228 cw(c58.176,76.754) 58.176,75.975 ; pad.0@59.357,75.745 cw(c59.913,75.189) 59.913,75.975 ; pad.0@59.357,76.24 ccw(c59.997,76.879) 59.997,75.975 ; U1.E4@60.289,75.975 ccw(c60.289,76.837) U1.E4@60.899,76.227 ; U1.E4@61.013,75.975 ccw(c61.013,76.113) U1.E4@61.111,76.015 ; U1.E4@61.551,75.975 58.176,75.975
  Bottom w0.3: pad.0@48.331,64.71 pad.0@50.871,64.71 ; pad.0@48.64,64.361 cw(c49.481,63.52) 49.481,64.71 ; pad.0@48.64,64.998 ccw(c49.335,65.693) 49.335,64.71 ; pad.0@48.852,64.149 cw(c50.205,62.796) pad.0@50.205,64.71 ; pad.0@48.852,65.21 ccw(c50.06,66.417) pad.0@50.06,64.71 ; pad.0@48.978,64.71 cw(c48.978,62.796) pad.0@50.331,64.149 ; pad.0@49.124,64.71 ccw(c49.124,66.417) pad.0@50.331,65.21 ; 49.703,64.71 cw(c49.703,63.52) pad.0@50.544,64.361 ; 49.848,64.71 ccw(c49.848,65.693) pad.0@50.544,64.998 ; 49.928,64.745 ccw(c50.067,65.263) pad.0@50.499,64.946 ; pad.0@50.201,65.034 cw(c49.324,65.503) 49.581,64.543 cw(c49.731,63.985) pad.0@50.223,64.287 ; pad.0@50.208,64.312 ccw(c49.207,63.75) 49.504,64.858 ccw(c49.687,65.541) pad.0@50.257,65.123
PC25: pad.0@48.322,67.22 pad.0@50.862,67.22 pad.0@59.06,77.262 U1.E5 | length 56.5
  Top w0.3: pad.0@48.331,67.25 52.651,67.25 ; pad.0@48.64,66.901 cw(c49.481,66.06) 49.481,67.25 ; pad.0@48.64,67.538 ccw(c49.335,68.233) 49.335,67.25 ; pad.0@48.852,66.689 cw(c50.205,65.336) pad.0@50.205,67.25 ; pad.0@48.852,67.75 ccw(c50.06,68.957) pad.0@50.06,67.25 ; pad.0@48.978,67.25 cw(c48.978,65.336) pad.0@50.331,66.689 ; pad.0@49.124,67.25 ccw(c49.124,68.957) pad.0@50.331,67.75 ; 49.703,67.25 cw(c49.703,66.06) pad.0@50.544,66.901 ; 49.848,67.25 ccw(c49.848,68.233) pad.0@50.544,67.538 ; 49.928,67.285 ccw(c50.067,67.803) pad.0@50.499,67.486 ; pad.0@50.201,67.574 cw(c49.324,68.043) 49.581,67.083 cw(c49.731,66.525) pad.0@50.223,66.827 ; pad.0@50.208,66.852 ccw(c49.207,66.29) 49.504,67.398 ccw(c49.687,68.081) pad.0@50.257,67.663 ; pad.0@51.18,67.538 ccw(c51.875,68.233) 51.875,67.25 ; pad.0@51.191,66.913 cw(c51.963,66.197) 51.963,67.25 ; pad.0@51.392,67.75 ccw(c52.6,68.957) 52.6,67.25 ; pad.0@51.411,66.709 cw(c52.651,65.558) 52.651,67.25 ; 58.123,77.245 ccw(c58.123,78.149) pad.0@58.762,77.51 ; 58.207,77.245 cw(c58.207,76.459) pad.0@58.762,77.015 ; pad.0@59.357,77.015 cw(c59.913,76.459) 59.913,77.245 ; pad.0@59.357,77.51 ccw(c59.997,78.149) 59.997,77.245 ; U1.E5@60.289,77.245 ccw(c60.289,78.107) U1.E5@60.899,77.497 ; U1.E5@61.013,77.245 ccw(c61.013,77.383) U1.E5@61.111,77.285 ; U1.E5@61.551,77.245 58.086,77.245 55.401,74.559 55.401,69.999 52.651,67.25
  Bottom w0.3: pad.0@48.331,67.25 pad.0@50.871,67.25 ; pad.0@48.64,66.901 cw(c49.481,66.06) 49.481,67.25 ; pad.0@48.64,67.538 ccw(c49.335,68.233) 49.335,67.25 ; pad.0@48.852,66.689 cw(c50.205,65.336) pad.0@50.205,67.25 ; pad.0@48.852,67.75 ccw(c50.06,68.957) pad.0@50.06,67.25 ; pad.0@48.978,67.25 cw(c48.978,65.336) pad.0@50.331,66.689 ; pad.0@49.124,67.25 ccw(c49.124,68.957) pad.0@50.331,67.75 ; 49.703,67.25 cw(c49.703,66.06) pad.0@50.544,66.901 ; 49.848,67.25 ccw(c49.848,68.233) pad.0@50.544,67.538 ; 49.928,67.285 ccw(c50.067,67.803) pad.0@50.499,67.486 ; pad.0@50.201,67.574 cw(c49.324,68.043) 49.581,67.083 cw(c49.731,66.525) pad.0@50.223,66.827 ; pad.0@50.208,66.852 ccw(c49.207,66.29) 49.504,67.398 ccw(c49.687,68.081) pad.0@50.257,67.663
PC26: pad.0@48.322,69.76 pad.0@50.862,69.76 pad.0@59.06,78.532 U1.E6 | length 54.8
  Top w0.3: pad.0@48.331,69.79 52.541,69.79 ; pad.0@48.64,69.441 cw(c49.481,68.6) 49.481,69.79 ; pad.0@48.64,70.078 ccw(c49.335,70.773) 49.335,69.79 ; pad.0@48.685,70.026 ccw(c49.117,70.343) 49.255,69.825 ; pad.0@48.852,69.229 cw(c50.205,67.876) pad.0@50.205,69.79 ; pad.0@48.852,70.29 ccw(c50.06,71.497) pad.0@50.06,69.79 ; pad.0@48.927,70.203 ccw(c49.496,70.621) 49.679,69.938 ccw(c49.976,68.83) pad.0@48.976,69.392 ; pad.0@48.961,69.367 cw(c49.453,69.065) 49.602,69.623 cw(c49.859,70.583) pad.0@48.983,70.114 ; pad.0@48.978,69.79 cw(c48.978,67.876) pad.0@50.331,69.229 ; pad.0@49.124,69.79 ccw(c49.124,71.497) pad.0@50.331,70.29 ; 49.703,69.79 cw(c49.703,68.6) pad.0@50.544,69.441 ; 49.848,69.79 ccw(c49.848,70.773) pad.0@50.544,70.078 ; pad.0@51.188,70.07 ccw(c51.841,70.692) 51.841,69.79 ; pad.0@51.206,69.469 cw(c51.895,68.887) 51.895,69.79 ; pad.0@51.405,70.277 ccw(c52.541,71.359) 52.541,69.79 ; pad.0@51.435,69.276 cw(c52.541,68.342) 52.541,69.79 ; 58.123,78.515 ccw(c58.123,79.419) pad.0@58.762,78.78 ; 58.207,78.515 cw(c58.207,77.729) pad.0@58.762,78.285 ; pad.0@59.357,78.285 cw(c59.913,77.729) 59.913,78.515 ; pad.0@59.357,78.78 ccw(c59.997,79.419) 59.997,78.515 ; U1.E6@60.289,78.515 ccw(c60.289,79.377) U1.E6@60.899,78.767 ; U1.E6@61.013,78.515 ccw(c61.013,78.653) U1.E6@61.111,78.555 ; U1.E6@61.551,78.515 58.116,78.515 54.501,74.899 54.501,71.749 52.541,69.79
  Bottom w0.3: pad.0@48.331,69.79 pad.0@50.871,69.79 ; pad.0@48.64,69.441 cw(c49.481,68.6) 49.481,69.79 ; pad.0@48.64,70.078 ccw(c49.335,70.773) 49.335,69.79 ; pad.0@48.685,70.026 ccw(c49.117,70.343) 49.255,69.825 ; pad.0@48.852,69.229 cw(c50.205,67.876) pad.0@50.205,69.79 ; pad.0@48.852,70.29 ccw(c50.06,71.497) pad.0@50.06,69.79 ; pad.0@48.927,70.203 ccw(c49.496,70.621) 49.679,69.938 ccw(c49.976,68.83) pad.0@48.976,69.392 ; pad.0@48.961,69.367 cw(c49.453,69.065) 49.602,69.623 cw(c49.859,70.583) pad.0@48.983,70.114 ; pad.0@48.978,69.79 cw(c48.978,67.876) pad.0@50.331,69.229 ; pad.0@49.124,69.79 ccw(c49.124,71.497) pad.0@50.331,70.29 ; 49.703,69.79 cw(c49.703,68.6) pad.0@50.544,69.441 ; 49.848,69.79 ccw(c49.848,70.773) pad.0@50.544,70.078
PC27: pad.0@48.322,72.3 pad.0@50.862,72.3 pad.0@59.06,79.802 U1.E7 | length 51.3
  Top w0.3: pad.0@48.331,72.33 52.291,72.33 ; pad.0@48.64,71.981 cw(c49.481,71.14) 49.481,72.33 ; pad.0@48.64,72.618 ccw(c49.335,73.313) 49.335,72.33 ; pad.0@48.685,72.566 ccw(c49.117,72.883) 49.255,72.365 ; pad.0@48.852,71.769 cw(c50.205,70.416) pad.0@50.205,72.33 ; pad.0@48.852,72.83 ccw(c50.06,74.037) pad.0@50.06,72.33 ; pad.0@48.927,72.743 ccw(c49.496,73.161) 49.679,72.478 ccw(c49.976,71.37) pad.0@48.976,71.932 ; pad.0@48.961,71.907 cw(c49.453,71.605) 49.602,72.163 cw(c49.859,73.123) pad.0@48.983,72.654 ; pad.0@48.978,72.33 cw(c48.978,70.416) pad.0@50.331,71.769 ; pad.0@49.124,72.33 ccw(c49.124,74.037) pad.0@50.331,72.83 ; 49.703,72.33 cw(c49.703,71.14) pad.0@50.544,71.981 ; 49.848,72.33 ccw(c49.848,73.313) pad.0@50.544,72.618 ; pad.0@51.464,72.746 ccw(c52.291,73.359) 52.291,72.33 ; pad.0@51.493,71.894 cw(c52.291,71.38) 52.291,72.33 ; 58.123,79.785 ccw(c58.123,80.689) pad.0@58.762,80.05 ; 58.207,79.785 cw(c58.207,78.999) pad.0@58.762,79.555 ; pad.0@59.357,79.555 cw(c59.913,78.999) 59.913,79.785 ; pad.0@59.357,80.05 ccw(c59.997,80.689) 59.997,79.785 ; U1.E7@60.289,79.785 ccw(c60.289,80.647) U1.E7@60.899,80.037 ; U1.E7@61.013,79.785 ccw(c61.013,79.923) U1.E7@61.111,79.825 ; U1.E7@61.551,79.785 58.056,79.785 53.701,75.429 53.701,73.739 52.291,72.33
  Bottom w0.3: pad.0@48.331,72.33 pad.0@50.871,72.33 ; pad.0@48.64,71.981 cw(c49.481,71.14) 49.481,72.33 ; pad.0@48.64,72.618 ccw(c49.335,73.313) 49.335,72.33 ; pad.0@48.685,72.566 ccw(c49.117,72.883) 49.255,72.365 ; pad.0@48.852,71.769 cw(c50.205,70.416) pad.0@50.205,72.33 ; pad.0@48.852,72.83 ccw(c50.06,74.037) pad.0@50.06,72.33 ; pad.0@48.927,72.743 ccw(c49.496,73.161) 49.679,72.478 ccw(c49.976,71.37) pad.0@48.976,71.932 ; pad.0@48.961,71.907 cw(c49.453,71.605) 49.602,72.163 cw(c49.859,73.123) pad.0@48.983,72.654 ; pad.0@48.978,72.33 cw(c48.978,70.416) pad.0@50.331,71.769 ; pad.0@49.124,72.33 ccw(c49.124,74.037) pad.0@50.331,72.83 ; 49.703,72.33 cw(c49.703,71.14) pad.0@50.544,71.981 ; 49.848,72.33 ccw(c49.848,73.313) pad.0@50.544,72.618
PC28: pad.0@48.322,74.84 pad.0@50.862,74.84 pad.0@59.06,81.072 U1.E8 | length 49
  Top w0.3: pad.0@48.331,74.87 52.091,74.87 ; pad.0@48.64,74.521 cw(c49.481,73.68) 49.481,74.87 ; pad.0@48.64,75.158 ccw(c49.335,75.853) 49.335,74.87 ; pad.0@48.685,75.106 ccw(c49.117,75.423) 49.255,74.905 ; pad.0@48.852,74.309 cw(c50.205,72.956) pad.0@50.205,74.87 ; pad.0@48.852,75.37 ccw(c50.06,76.577) pad.0@50.06,74.87 ; pad.0@48.927,75.283 ccw(c49.496,75.701) 49.679,75.018 ccw(c49.976,73.91) pad.0@48.976,74.472 ; pad.0@48.961,74.447 cw(c49.453,74.145) 49.602,74.703 cw(c49.859,75.663) pad.0@48.983,75.194 ; pad.0@48.978,74.87 cw(c48.978,72.956) pad.0@50.331,74.309 ; pad.0@49.124,74.87 ccw(c49.124,76.577) pad.0@50.331,75.37 ; 49.703,74.87 cw(c49.703,73.68) pad.0@50.544,74.521 ; 49.848,74.87 ccw(c49.848,75.853) pad.0@50.544,75.158 ; pad.0@51.516,75.207 ccw(c52.091,75.529) 52.091,74.87 ; pad.0@51.54,74.52 cw(c52.091,74.261) 52.091,74.87 ; pad.0@58.73,81.282 cw(c58.276,81.621) 58.276,81.055 ; pad.0@58.747,80.841 ccw(c58.276,80.429) 58.276,81.055 ; pad.0@59.357,80.825 cw(c59.913,80.269) 59.913,81.055 ; pad.0@59.357,81.32 ccw(c59.997,81.959) 59.997,81.055 ; U1.E8@60.289,81.055 ccw(c60.289,81.917) U1.E8@60.899,81.307 ; U1.E8@61.013,81.055 ccw(c61.013,81.193) U1.E8@61.111,81.095 ; U1.E8@61.551,81.055 58.276,81.055 ; 52.091,74.87 58.276,81.055
  Bottom w0.3: pad.0@48.331,74.87 pad.0@50.871,74.87 ; pad.0@48.64,74.521 cw(c49.481,73.68) 49.481,74.87 ; pad.0@48.64,75.158 ccw(c49.335,75.853) 49.335,74.87 ; pad.0@48.685,75.106 ccw(c49.117,75.423) 49.255,74.905 ; pad.0@48.852,74.309 cw(c50.205,72.956) pad.0@50.205,74.87 ; pad.0@48.852,75.37 ccw(c50.06,76.577) pad.0@50.06,74.87 ; pad.0@48.927,75.283 ccw(c49.496,75.701) 49.679,75.018 ccw(c49.976,73.91) pad.0@48.976,74.472 ; pad.0@48.961,74.447 cw(c49.453,74.145) 49.602,74.703 cw(c49.859,75.663) pad.0@48.983,75.194 ; pad.0@48.978,74.87 cw(c48.978,72.956) pad.0@50.331,74.309 ; pad.0@49.124,74.87 ccw(c49.124,76.577) pad.0@50.331,75.37 ; 49.703,74.87 cw(c49.703,73.68) pad.0@50.544,74.521 ; 49.848,74.87 ccw(c49.848,75.853) pad.0@50.544,75.158
PC29: pad.0@48.322,77.38 pad.0@50.862,77.38 pad.0@59.06,82.342 U1.E9 | length 51.8
  Top w0.3: pad.0@48.341,77.36 pad.0@50.881,77.36 ; pad.0@48.64,77.061 cw(c49.36,76.341) 49.36,77.36 ; pad.0@48.64,77.698 ccw(c49.456,78.514) 49.456,77.36 ; pad.0@48.688,77.118 cw(c49.113,76.816) 49.248,77.32 ; pad.0@48.852,76.849 cw(c50.084,75.617) pad.0@50.084,77.36 ; pad.0@48.852,77.91 ccw(c50.18,79.238) pad.0@50.18,77.36 ; pad.0@48.933,76.944 cw(c49.489,76.548) 49.666,77.208 cw(c49.956,78.291) pad.0@48.977,77.745 ; pad.0@48.955,77.781 ccw(c49.46,78.102) 49.615,77.524 ccw(c49.879,76.538) pad.0@48.982,77.023 ; pad.0@49.003,77.36 ccw(c49.003,79.238) pad.0@50.331,77.91 ; pad.0@49.099,77.36 cw(c49.099,75.617) pad.0@50.331,76.849 ; 49.727,77.36 ccw(c49.727,78.514) pad.0@50.544,77.698 ; 49.823,77.36 cw(c49.823,76.341) pad.0@50.544,77.061 ; pad.0@50.871,77.41 53.241,77.41 58.156,82.325 ; pad.0@51.18,77.061 cw(c52.021,76.22) 52.021,77.41 ; pad.0@51.18,77.698 ccw(c51.875,78.393) 51.875,77.41 ; pad.0@51.392,76.849 cw(c52.745,75.496) 52.745,77.41 ; pad.0@51.392,77.91 ccw(c52.6,79.117) 52.6,77.41 ; 58.207,82.325 cw(c58.207,81.539) pad.0@58.762,82.095 ; pad.0@58.756,82.583 cw(c58.156,83.15) 58.156,82.325 ; pad.0@59.357,82.095 cw(c59.913,81.539) 59.913,82.325 ; pad.0@59.357,82.59 ccw(c59.997,83.229) 59.997,82.325 ; U1.E9@60.289,82.325 ccw(c60.289,83.187) U1.E9@60.899,82.577 ; U1.E9@61.013,82.325 ccw(c61.013,82.463) U1.E9@61.111,82.365 ; U1.E9@61.551,82.325 58.156,82.325
  Bottom w0.3: pad.0@48.341,77.36 pad.0@50.881,77.36 ; pad.0@48.64,77.061 cw(c49.36,76.341) 49.36,77.36 ; pad.0@48.64,77.698 ccw(c49.456,78.514) 49.456,77.36 ; pad.0@48.688,77.118 cw(c49.113,76.816) 49.248,77.32 ; pad.0@48.852,76.849 cw(c50.084,75.617) pad.0@50.084,77.36 ; pad.0@48.852,77.91 ccw(c50.18,79.238) pad.0@50.18,77.36 ; pad.0@48.933,76.944 cw(c49.489,76.548) 49.666,77.208 cw(c49.956,78.291) pad.0@48.977,77.745 ; pad.0@48.955,77.781 ccw(c49.46,78.102) 49.615,77.524 ccw(c49.879,76.538) pad.0@48.982,77.023 ; pad.0@49.003,77.36 ccw(c49.003,79.238) pad.0@50.331,77.91 ; pad.0@49.099,77.36 cw(c49.099,75.617) pad.0@50.331,76.849 ; 49.727,77.36 ccw(c49.727,78.514) pad.0@50.544,77.698 ; 49.823,77.36 cw(c49.823,76.341) pad.0@50.544,77.061
PC30: pad.0@48.322,79.92 pad.0@50.862,79.92 pad.0@59.06,83.612 U1.E10 | length 51.4
  Top w0.3: pad.0@48.331,79.95 54.501,79.95 58.146,83.595 ; pad.0@48.64,79.601 cw(c49.481,78.76) 49.481,79.95 ; pad.0@48.64,80.238 ccw(c49.335,80.933) 49.335,79.95 ; pad.0@48.685,80.186 ccw(c49.117,80.503) 49.255,79.985 ; pad.0@48.852,79.389 cw(c50.205,78.036) pad.0@50.205,79.95 ; pad.0@48.852,80.45 ccw(c50.06,81.657) pad.0@50.06,79.95 ; pad.0@48.927,80.363 ccw(c49.496,80.781) 49.679,80.098 ccw(c49.976,78.99) pad.0@48.976,79.552 ; pad.0@48.961,79.527 cw(c49.453,79.225) 49.602,79.783 cw(c49.859,80.743) pad.0@48.983,80.274 ; pad.0@48.978,79.95 cw(c48.978,78.036) pad.0@50.331,79.389 ; pad.0@49.124,79.95 ccw(c49.124,81.657) pad.0@50.331,80.45 ; 49.703,79.95 cw(c49.703,78.76) pad.0@50.544,79.601 ; 49.848,79.95 ccw(c49.848,80.933) pad.0@50.544,80.238 ; pad.0@51.18,79.601 cw(c52.021,78.76) 52.021,79.95 ; pad.0@51.18,80.238 ccw(c51.875,80.933) 51.875,79.95 ; pad.0@51.392,79.389 cw(c52.745,78.036) 52.745,79.95 ; pad.0@51.392,80.45 ccw(c52.6,81.657) 52.6,79.95 ; 58.207,83.595 cw(c58.207,82.809) pad.0@58.762,83.365 ; pad.0@58.758,83.855 cw(c58.146,84.444) 58.146,83.595 ; pad.0@59.357,83.365 cw(c59.913,82.809) 59.913,83.595 ; pad.0@59.357,83.86 ccw(c59.997,84.499) 59.997,83.595 ; U1.E10@60.289,83.595 ccw(c60.289,84.457) U1.E10@60.899,83.847 ; U1.E10@61.013,83.595 ccw(c61.013,83.733) U1.E10@61.111,83.635 ; U1.E10@61.551,83.595 58.146,83.595
  Bottom w0.3: pad.0@48.331,79.95 pad.0@50.871,79.95 ; pad.0@48.64,79.601 cw(c49.481,78.76) 49.481,79.95 ; pad.0@48.64,80.238 ccw(c49.335,80.933) 49.335,79.95 ; pad.0@48.685,80.186 ccw(c49.117,80.503) 49.255,79.985 ; pad.0@48.852,79.389 cw(c50.205,78.036) pad.0@50.205,79.95 ; pad.0@48.852,80.45 ccw(c50.06,81.657) pad.0@50.06,79.95 ; pad.0@48.927,80.363 ccw(c49.496,80.781) 49.679,80.098 ccw(c49.976,78.99) pad.0@48.976,79.552 ; pad.0@48.961,79.527 cw(c49.453,79.225) 49.602,79.783 cw(c49.859,80.743) pad.0@48.983,80.274 ; pad.0@48.978,79.95 cw(c48.978,78.036) pad.0@50.331,79.389 ; pad.0@49.124,79.95 ccw(c49.124,81.657) pad.0@50.331,80.45 ; 49.703,79.95 cw(c49.703,78.76) pad.0@50.544,79.601 ; 49.848,79.95 ccw(c49.848,80.933) pad.0@50.544,80.238
PC31: pad.0@48.322,82.46 pad.0@50.862,82.46 pad.0@59.06,84.882 U1.E11 | length 50.8
  Top w0.3: pad.0@48.331,82.49 55.821,82.49 58.196,84.865 ; pad.0@48.64,82.141 cw(c49.481,81.3) 49.481,82.49 ; pad.0@48.64,82.778 ccw(c49.335,83.473) 49.335,82.49 ; pad.0@48.685,82.726 ccw(c49.117,83.043) 49.255,82.525 ; pad.0@48.852,81.929 cw(c50.205,80.576) pad.0@50.205,82.49 ; pad.0@48.852,82.99 ccw(c50.06,84.197) pad.0@50.06,82.49 ; pad.0@48.927,82.903 ccw(c49.496,83.321) 49.679,82.638 ccw(c49.976,81.53) pad.0@48.976,82.092 ; pad.0@48.961,82.067 cw(c49.453,81.765) 49.602,82.323 cw(c49.859,83.283) pad.0@48.983,82.814 ; pad.0@48.978,82.49 cw(c48.978,80.576) pad.0@50.331,81.929 ; pad.0@49.124,82.49 ccw(c49.124,84.197) pad.0@50.331,82.99 ; 49.703,82.49 cw(c49.703,81.3) pad.0@50.544,82.141 ; 49.848,82.49 ccw(c49.848,83.473) pad.0@50.544,82.778 ; pad.0@51.18,82.141 cw(c52.021,81.3) 52.021,82.49 ; pad.0@51.18,82.778 ccw(c51.875,83.473) 51.875,82.49 ; pad.0@51.392,81.929 cw(c52.745,80.576) 52.745,82.49 ; pad.0@51.392,82.99 ccw(c52.6,84.197) 52.6,82.49 ; 58.207,84.865 cw(c58.207,84.079) pad.0@58.762,84.635 ; pad.0@58.747,85.114 cw(c58.196,85.6) 58.196,84.865 ; pad.0@59.357,84.635 cw(c59.913,84.079) 59.913,84.865 ; pad.0@59.357,85.13 ccw(c59.997,85.769) 59.997,84.865 ; U1.E11@60.289,84.865 ccw(c60.289,85.727) U1.E11@60.899,85.117 ; U1.E11@61.013,84.865 ccw(c61.013,85.003) U1.E11@61.111,84.905 ; U1.E11@61.551,84.865 58.196,84.865
  Bottom w0.3: pad.0@48.331,82.49 pad.0@50.871,82.49 ; pad.0@48.64,82.141 cw(c49.481,81.3) 49.481,82.49 ; pad.0@48.64,82.778 ccw(c49.335,83.473) 49.335,82.49 ; pad.0@48.685,82.726 ccw(c49.117,83.043) 49.255,82.525 ; pad.0@48.852,81.929 cw(c50.205,80.576) pad.0@50.205,82.49 ; pad.0@48.852,82.99 ccw(c50.06,84.197) pad.0@50.06,82.49 ; pad.0@48.927,82.903 ccw(c49.496,83.321) 49.679,82.638 ccw(c49.976,81.53) pad.0@48.976,82.092 ; pad.0@48.961,82.067 cw(c49.453,81.765) 49.602,82.323 cw(c49.859,83.283) pad.0@48.983,82.814 ; pad.0@48.978,82.49 cw(c48.978,80.576) pad.0@50.331,81.929 ; pad.0@49.124,82.49 ccw(c49.124,84.197) pad.0@50.331,82.99 ; 49.703,82.49 cw(c49.703,81.3) pad.0@50.544,82.141 ; 49.848,82.49 ccw(c49.848,83.473) pad.0@50.544,82.778
RTCK: U1.11
RX_N: J2.6 pad.0@102.032,98.827 pad.0@111.822,110.4 U1.W3 | length 94.9
  Top w0.3: J2.6@93.709,143.988 cw(c93.709,142.531) 94.74,143.561 ; J2.6@93.709,144.688 93.709,144.591 v2(95.376,142.925) 96.776,142.925 97.697,142.003 97.697,142 98.352,141.346 98.355,141.346 98.401,141.3 100.601,141.3 111.701,130.2 111.701,118.52 113.251,116.97 113.251,111.85 pad.0@111.831,110.43 ; J2.6@94.109,144.688 ccw(c95.308,144.688) 94.46,143.84 ; J2.6@94.409,144.688 ccw(c96.332,144.688) 94.972,143.328 ; 94.587,143.996 ccw(c95.859,144.731) v2@95.479,143.311 ; 94.93,143.402 ccw(c95.14,143.524) v2@95.229,143.297 ; 94.949,143.369 ccw(c95.594,143.741) v2@95.401,143.021 ; v2@94.976,142.925 ccw(c94.01,142.925) 94.693,143.608 ccw(c95.376,144.291) v2@95.376,143.325 ; v2@95.658,142.642 cw(c96.341,141.959) 96.341,142.925 cw(c96.341,143.891) v2@95.658,143.208 ; U1.W3@99.551,98.835 102.436,98.835 103.961,100.36 103.961,105.56 109.743,111.342 110.889,111.342 pad.0@111.831,110.4 ; U1.W3@99.992,98.875 ccw(c100.089,98.973) U1.W3@100.089,98.835 ; U1.W3@100.204,99.087 ccw(c100.813,99.697) U1.W3@100.813,98.835 ; 101.119,98.835 cw(c101.119,97.964) pad.0@101.735,98.58 ; 101.155,98.835 ccw(c101.155,99.654) pad.0@101.735,99.075 ; 110.48,111.342 cw(c110.48,110.122) pad.0@111.675,110.369 ; pad.0@111.095,110.587 ccw(c110.331,110.784) 110.889,111.342 ccw(c111.458,111.91) pad.0@111.646,111.129 ; pad.0@111.822,110.85 ccw(c111.822,111.886) pad.0@112.555,111.153 ; pad.0@111.822,111.15 ccw(c111.822,112.91) 113.067,111.665 ; pad.0@112.272,110.4 cw(c113.408,110.4) pad.0@112.605,111.203 ; pad.0@112.572,110.4 cw(c114.432,110.4) 113.117,111.715 ; 94.943,143.379 cw(c94.543,143.148) 94.989,143.028 ccw(c94.543,143.148) 94.943,143.379
  Bottom w0.3: J2.6@93.709,143.988 cw(c93.709,142.531) 94.74,143.561 ; J2.6@93.709,144.591 v2(95.376,142.925) ; J2.6@94.109,144.688 ccw(c95.308,144.688) 94.46,143.84 ; J2.6@94.409,144.688 ccw(c96.332,144.688) 94.972,143.328 ; 94.587,143.996 ccw(c95.859,144.731) v2@95.479,143.311 ; 94.943,143.379 cw(c94.543,143.148) v2@94.989,143.028 ; 94.949,143.369 ccw(c95.594,143.741) v2@95.401,143.021 ; v2@94.976,142.925 ccw(c94.01,142.925) 94.693,143.608 ccw(c95.376,144.291) v2@95.376,143.325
